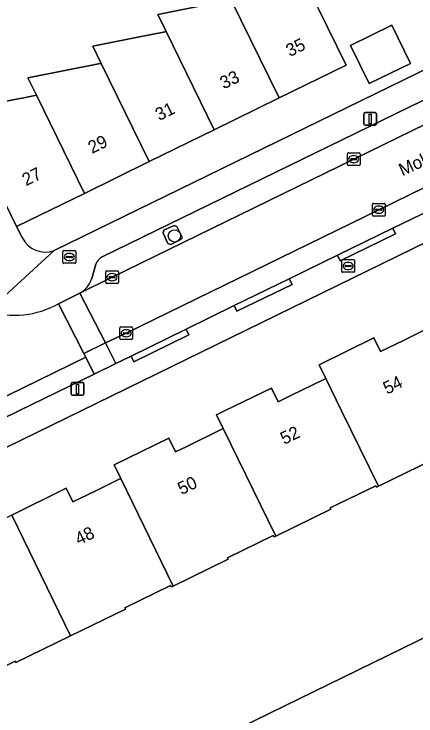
# Model space of a CAD drawing. Extents: x 160455 to 162082, y 388339 to 389736.
# Drawn here: x 160872.8 to 160904.5, y 388725.9 to 388781.3 of the extents above; entities that cross this region are included whole.
import ezdxf

# ---------------------------------------------------------------- set-up
doc = ezdxf.new("R2010")
doc.units = 0
for name, color, linetype in [('IMGEO_Boom', 7, 'Continuous'), ('IMGEO_Brandkraan', 7, 'Continuous'), ('IMGEO_Erf', 7, 'Continuous'), ('IMGEO_Groenvoorziening', 7, 'Continuous'), ('IMGEO_Kolk', 7, 'Continuous'), ('IMGEO_Lichtmast', 7, 'Continuous'), ('IMGEO_Openbare_ruimte_label', 7, 'Continuous'), ('IMGEO_Pand', 7, 'Continuous'), ('IMGEO_Pand_nummerreeks', 7, 'Continuous'), ('IMGEO_Parkeervlak_open', 7, 'Continuous'), ('IMGEO_Rijbaan_lokaal_gesloten', 7, 'Continuous'), ('IMGEO_Rijbaan_lokaal_open', 7, 'Continuous'), ('IMGEO_Voetpad_open', 7, 'Continuous'), ('IMGEO_Waterloop', 7, 'Continuous')]:
    doc.layers.add(name, color=color, linetype=linetype)

msp = doc.modelspace()

# ---------------------------------------------------------------- linework, layer by layer
at = {"layer": 'IMGEO_Boom'}
msp.add_circle((160885.427, 388763.797), 0.489, dxfattribs=at)
at = {"layer": 'IMGEO_Brandkraan'}
for p, q in [((160876.642, 388761.709), (160876.642, 388762.561)), ((160876.717, 388762.635), (160877.569, 388762.635)), ((160877.643, 388762.561), (160877.643, 388761.709)), ((160876.901, 388762.129), (160876.901, 388762.141)), ((160877.339, 388762.092), (160876.941, 388762.092)), ((160876.944, 388762.178), (160877.342, 388762.178)), ((160877.13, 388762.415), (160877.155, 388762.415)), ((160877.385, 388762.141), (160877.385, 388762.129)), ((160877.569, 388761.635), (160876.717, 388761.635)), ((160877.153, 388761.855), (160877.128, 388761.855)), ((160898.623, 388761.001), (160898.623, 388761.853)), ((160898.698, 388761.927), (160899.55, 388761.927)), ((160898.882, 388761.421), (160898.882, 388761.433)), ((160898.925, 388761.47), (160899.323, 388761.47)), ((160899.111, 388761.707), (160899.136, 388761.707)), ((160899.366, 388761.433), (160899.366, 388761.421)), ((160899.624, 388761.853), (160899.624, 388761.001)), ((160899.55, 388760.927), (160898.698, 388760.927)), ((160899.32, 388761.384), (160898.922, 388761.384)), ((160899.134, 388761.147), (160899.109, 388761.147))]:
    msp.add_line(p, q, dxfattribs=at)
for points in [[(160876.642, 388761.709), (160876.642, 388762.561)], [(160876.717, 388762.635), (160877.569, 388762.635)], [(160877.643, 388762.561), (160877.643, 388761.709)], [(160877.569, 388761.635), (160876.717, 388761.635)], [(160898.623, 388761.001), (160898.623, 388761.853)], [(160898.698, 388761.927), (160899.55, 388761.927)], [(160899.624, 388761.853), (160899.624, 388761.001)], [(160899.55, 388760.927), (160898.698, 388760.927)]]:
    msp.add_lwpolyline(points, dxfattribs=at)
for centre, radius, start, end in [((160876.719, 388762.559), 0.0765, 91.552, 178.448), ((160876.719, 388762.559), 0.0765, 91.552, 178.448), ((160877.567, 388762.559), 0.0765, 1.552, 88.448), ((160877.567, 388762.559), 0.0765, 1.552, 88.448), ((160876.941, 388762.138), 0.0403, 85.8775, 175.7526), ((160876.938, 388762.128), 0.0366, 178.938, 274.7102), ((160877.342, 388762.135), 0.043, 264.8664, 352.4533), ((160877.346, 388762.14), 0.0386, 1.7309, 96.639), ((160876.719, 388761.711), 0.0765, 181.552, 268.448), ((160876.719, 388761.711), 0.0765, 181.552, 268.448), ((160877.567, 388761.711), 0.0765, 271.552, 358.448), ((160877.567, 388761.711), 0.0765, 271.552, 358.448), ((160898.7, 388761.851), 0.0765, 91.552, 178.448), ((160898.7, 388761.851), 0.0765, 91.552, 178.448), ((160898.922, 388761.43), 0.0403, 85.8775, 175.7526), ((160898.919, 388761.42), 0.0366, 178.938, 274.7102), ((160899.323, 388761.427), 0.043, 264.8664, 352.4533), ((160899.327, 388761.432), 0.0386, 1.7309, 96.639), ((160899.548, 388761.851), 0.0765, 1.552, 88.448), ((160899.548, 388761.851), 0.0765, 1.552, 88.448), ((160898.7, 388761.003), 0.0765, 181.552, 268.448), ((160898.7, 388761.003), 0.0765, 181.552, 268.448), ((160899.548, 388761.003), 0.0765, 271.552, 358.448), ((160899.548, 388761.003), 0.0765, 271.552, 358.448)]:
    msp.add_arc(centre, radius, start, end, dxfattribs=at)
for centre, major_axis, ratio, start_param, end_param in [((160877.129, 388762.135), (-0.387, 0.002), 0.722429, 4.712389, 7.853982), ((160877.154, 388762.135), (-0.39, 0.002), 0.717154, 1.570796, 4.712389), ((160899.11, 388761.427), (-0.387, 0.002), 0.722429, 4.712389, 7.853982), ((160899.135, 388761.427), (-0.39, 0.002), 0.717154, 1.570796, 4.712389)]:
    msp.add_ellipse(centre, major_axis=major_axis, ratio=ratio, start_param=start_param, end_param=end_param, dxfattribs=at)
at = {"layer": 'IMGEO_Erf'}
for points in [[(160875.947, 388762.656), (160922.127, 388785.223)], [(160868.516, 388773.685), (160872.989, 388774.58), (160873.419, 388774.666), (160874.321, 388774.847), (160874.546, 388774.892), (160873.883, 388776.248), (160876.661, 388776.801), (160879.438, 388777.354), (160879.663, 388777.399), (160879, 388778.755), (160882.554, 388779.462), (160884.555, 388779.861), (160884.78, 388779.906), (160884.117, 388781.262), (160887.932, 388782.021)], [(160896.769, 388781.756), (160898.969, 388777.266), (160893.681, 388774.675), (160888.563, 388772.168), (160883.446, 388769.66), (160878.329, 388767.153), (160872.977, 388764.531), (160873.431, 388763.666)], [(160937.925, 388772.412), (160936.05, 388776.299), (160935.249, 388777.96), (160929.117, 388774.962), (160878.066, 388750), (160811.085, 388717.249)], [(160766.298, 388664.267), (160941.708, 388750), (160948.921, 388753.525), (160948.021, 388755.303), (160947.977, 388755.282), (160946.576, 388758.143), (160949.559, 388759.604), (160949.905, 388758.897), (160955.447, 388761.62), (160953.756, 388765.074), (160956.812, 388766.571), (160958.502, 388763.122), (160958.774, 388763.255), (160957.453, 388765.953), (160960.515, 388767.453), (160961.835, 388764.759), (160968.352, 388767.962)], [(160872.599, 388741.787), (160876.898, 388743.896), (160877.427, 388742.819), (160879.228, 388743.7), (160881.029, 388744.581), (160881.194, 388744.662), (160880.669, 388745.741), (160884.978, 388747.842), (160885.505, 388746.764), (160886.34, 388747.173), (160889.113, 388748.532), (160889.269, 388748.608), (160888.742, 388749.687), (160889.385, 388750), (160893.068, 388751.796), (160893.594, 388750.717), (160894.654, 388751.238), (160897.195, 388752.486), (160897.351, 388752.562), (160896.824, 388753.641), (160901.153, 388755.751), (160901.679, 388754.672), (160903.479, 388755.554), (160905.278, 388756.436)], [(160905.828, 388746.18), (160901.5, 388744.065), (160901.355, 388743.994), (160901.303, 388744.102), (160897.696, 388742.348), (160897.749, 388742.24), (160893.408, 388740.129), (160893.261, 388740.058), (160893.209, 388740.166), (160889.603, 388738.412), (160889.655, 388738.304), (160885.316, 388736.194), (160885.168, 388736.122), (160885.115, 388736.23), (160881.509, 388734.476), (160881.562, 388734.368), (160877.233, 388732.263), (160872.919, 388730.166), (160872.867, 388730.274), (160869.261, 388728.52)]]:
    msp.add_lwpolyline(points, dxfattribs=at)
msp.add_lwpolyline([(160899.294, 388778.812), (160902.551, 388780.407), (160904.026, 388777.398), (160900.769, 388775.802)], close=True, dxfattribs=at)
msp.add_arc((160875.231, 388764.512), 1.989, 205.1625, 291.0934, dxfattribs=at)
at = {"layer": 'IMGEO_Groenvoorziening'}
msp.add_lwpolyline([(160886.012, 388763.755), (160885.625, 388764.551), (160885.403, 388764.625), (160884.59, 388764.237), (160884.53, 388764.012), (160884.92, 388763.211), (160885.146, 388763.123), (160885.938, 388763.517)], dxfattribs=at)
msp.add_arc((160885.855, 388763.673), 0.177, 298.0228, 27.4337, dxfattribs=at)
at = {"layer": 'IMGEO_Kolk'}
for p, q in [((160899.059, 388769.421), (160899.059, 388770.273)), ((160899.134, 388770.347), (160899.986, 388770.347)), ((160900.06, 388770.273), (160900.06, 388769.421)), ((160899.318, 388769.841), (160899.318, 388769.853)), ((160899.756, 388769.804), (160899.358, 388769.804)), ((160899.361, 388769.89), (160899.759, 388769.89)), ((160899.547, 388770.127), (160899.572, 388770.127)), ((160899.802, 388769.853), (160899.802, 388769.841)), ((160899.986, 388769.347), (160899.134, 388769.347)), ((160899.57, 388769.567), (160899.545, 388769.567)), ((160901.034, 388765.438), (160901.034, 388766.29)), ((160901.109, 388766.364), (160901.961, 388766.364)), ((160901.293, 388765.858), (160901.293, 388765.87)), ((160901.336, 388765.907), (160901.734, 388765.907)), ((160901.522, 388766.144), (160901.547, 388766.144)), ((160901.777, 388765.87), (160901.777, 388765.858)), ((160902.035, 388766.29), (160902.035, 388765.438)), ((160901.961, 388765.364), (160901.109, 388765.364)), ((160901.731, 388765.821), (160901.333, 388765.821)), ((160901.545, 388765.584), (160901.52, 388765.584)), ((160880.009, 388760.12), (160880.009, 388760.972)), ((160880.084, 388761.046), (160880.936, 388761.046)), ((160881.01, 388760.972), (160881.01, 388760.12)), ((160880.268, 388760.54), (160880.268, 388760.552)), ((160880.706, 388760.503), (160880.308, 388760.503)), ((160880.311, 388760.589), (160880.709, 388760.589)), ((160880.497, 388760.826), (160880.522, 388760.826)), ((160880.752, 388760.552), (160880.752, 388760.54)), ((160880.936, 388760.046), (160880.084, 388760.046)), ((160880.52, 388760.266), (160880.495, 388760.266)), ((160881.116, 388755.698), (160881.116, 388756.55)), ((160881.191, 388756.624), (160882.043, 388756.624)), ((160882.117, 388756.55), (160882.117, 388755.698)), ((160881.375, 388756.118), (160881.375, 388756.13)), ((160881.813, 388756.081), (160881.415, 388756.081)), ((160881.418, 388756.167), (160881.816, 388756.167)), ((160881.604, 388756.404), (160881.629, 388756.404)), ((160881.859, 388756.13), (160881.859, 388756.118)), ((160882.043, 388755.624), (160881.191, 388755.624)), ((160881.627, 388755.844), (160881.602, 388755.844))]:
    msp.add_line(p, q, dxfattribs=at)
for points in [[(160899.059, 388769.421), (160899.059, 388770.273)], [(160899.134, 388770.347), (160899.986, 388770.347)], [(160900.06, 388770.273), (160900.06, 388769.421)], [(160899.986, 388769.347), (160899.134, 388769.347)], [(160901.034, 388765.438), (160901.034, 388766.29)], [(160901.109, 388766.364), (160901.961, 388766.364)], [(160902.035, 388766.29), (160902.035, 388765.438)], [(160901.961, 388765.364), (160901.109, 388765.364)], [(160880.009, 388760.12), (160880.009, 388760.972)], [(160880.084, 388761.046), (160880.936, 388761.046)], [(160881.01, 388760.972), (160881.01, 388760.12)], [(160880.936, 388760.046), (160880.084, 388760.046)], [(160881.116, 388755.698), (160881.116, 388756.55)], [(160881.191, 388756.624), (160882.043, 388756.624)], [(160882.117, 388756.55), (160882.117, 388755.698)], [(160882.043, 388755.624), (160881.191, 388755.624)]]:
    msp.add_lwpolyline(points, dxfattribs=at)
for centre, radius, start, end in [((160899.136, 388770.271), 0.0765, 91.552, 178.448), ((160899.136, 388770.271), 0.0765, 91.552, 178.448), ((160899.984, 388770.271), 0.0765, 1.552, 88.448), ((160899.984, 388770.271), 0.0765, 1.552, 88.448), ((160899.358, 388769.85), 0.0403, 85.8775, 175.7526), ((160899.355, 388769.84), 0.0366, 178.938, 274.7102), ((160899.759, 388769.847), 0.043, 264.8664, 352.4533), ((160899.763, 388769.852), 0.0386, 1.7309, 96.639), ((160899.136, 388769.423), 0.0765, 181.552, 268.448), ((160899.136, 388769.423), 0.0765, 181.552, 268.448), ((160899.984, 388769.423), 0.0765, 271.552, 358.448), ((160899.984, 388769.423), 0.0765, 271.552, 358.448), ((160901.111, 388766.288), 0.0765, 91.552, 178.448), ((160901.111, 388766.288), 0.0765, 91.552, 178.448), ((160901.333, 388765.867), 0.0403, 85.8775, 175.7526), ((160901.33, 388765.857), 0.0366, 178.938, 274.7102), ((160901.734, 388765.864), 0.043, 264.8664, 352.4533), ((160901.738, 388765.869), 0.0386, 1.7309, 96.639), ((160901.959, 388766.288), 0.0765, 1.552, 88.448), ((160901.959, 388766.288), 0.0765, 1.552, 88.448), ((160901.111, 388765.44), 0.0765, 181.552, 268.448), ((160901.111, 388765.44), 0.0765, 181.552, 268.448), ((160901.959, 388765.44), 0.0765, 271.552, 358.448), ((160901.959, 388765.44), 0.0765, 271.552, 358.448), ((160880.086, 388760.97), 0.0765, 91.552, 178.448), ((160880.086, 388760.97), 0.0765, 91.552, 178.448), ((160880.934, 388760.97), 0.0765, 1.552, 88.448), ((160880.934, 388760.97), 0.0765, 1.552, 88.448), ((160880.308, 388760.549), 0.0403, 85.8775, 175.7526), ((160880.305, 388760.539), 0.0366, 178.938, 274.7102), ((160880.709, 388760.546), 0.043, 264.8664, 352.4533), ((160880.713, 388760.551), 0.0386, 1.7309, 96.639), ((160880.086, 388760.122), 0.0765, 181.552, 268.448), ((160880.086, 388760.122), 0.0765, 181.552, 268.448), ((160880.934, 388760.122), 0.0765, 271.552, 358.448), ((160880.934, 388760.122), 0.0765, 271.552, 358.448), ((160881.193, 388756.548), 0.0765, 91.552, 178.448), ((160881.193, 388756.548), 0.0765, 91.552, 178.448), ((160882.041, 388756.548), 0.0765, 1.552, 88.448), ((160882.041, 388756.548), 0.0765, 1.552, 88.448), ((160881.415, 388756.127), 0.0403, 85.8775, 175.7526), ((160881.412, 388756.117), 0.0366, 178.938, 274.7102), ((160881.816, 388756.124), 0.043, 264.8664, 352.4533), ((160881.82, 388756.129), 0.0386, 1.7309, 96.639), ((160881.193, 388755.7), 0.0765, 181.552, 268.448), ((160881.193, 388755.7), 0.0765, 181.552, 268.448), ((160882.041, 388755.7), 0.0765, 271.552, 358.448), ((160882.041, 388755.7), 0.0765, 271.552, 358.448)]:
    msp.add_arc(centre, radius, start, end, dxfattribs=at)
for centre, major_axis, ratio, start_param, end_param in [((160899.546, 388769.847), (-0.387, 0.002), 0.722429, 4.712389, 7.853982), ((160899.571, 388769.847), (-0.39, 0.002), 0.717154, 1.570796, 4.712389), ((160901.521, 388765.864), (-0.387, 0.002), 0.722429, 4.712389, 7.853982), ((160901.546, 388765.864), (-0.39, 0.002), 0.717154, 1.570796, 4.712389), ((160880.496, 388760.546), (-0.387, 0.002), 0.722429, 4.712389, 7.853982), ((160880.521, 388760.546), (-0.39, 0.002), 0.717154, 1.570796, 4.712389), ((160881.603, 388756.124), (-0.387, 0.002), 0.722429, 4.712389, 7.853982), ((160881.628, 388756.124), (-0.39, 0.002), 0.717154, 1.570796, 4.712389)]:
    msp.add_ellipse(centre, major_axis=major_axis, ratio=ratio, start_param=start_param, end_param=end_param, dxfattribs=at)
at = {"layer": 'IMGEO_Lichtmast'}
for p, q in [((160900.353, 388772.618), (160900.353, 388773.418)), ((160900.353, 388773.418), (160900.353, 388772.618)), ((160900.453, 388773.518), (160901.243, 388773.518)), ((160901.243, 388773.518), (160900.453, 388773.518)), ((160901.343, 388773.418), (160901.343, 388772.618)), ((160901.343, 388772.618), (160901.343, 388773.418)), ((160901.243, 388772.518), (160900.453, 388772.518)), ((160900.453, 388772.518), (160901.243, 388772.518)), ((160877.287, 388751.332), (160877.287, 388752.132)), ((160877.287, 388752.132), (160877.287, 388751.332)), ((160877.387, 388752.232), (160878.177, 388752.232)), ((160878.177, 388752.232), (160877.387, 388752.232)), ((160878.277, 388752.132), (160878.277, 388751.332)), ((160878.277, 388751.332), (160878.277, 388752.132)), ((160878.177, 388751.232), (160877.387, 388751.232)), ((160877.387, 388751.232), (160878.177, 388751.232))]:
    msp.add_line(p, q, dxfattribs=at)
for points in [[(160900.773, 388773.393), (160900.923, 388773.393), (160900.923, 388772.643), (160900.773, 388772.643), (160900.773, 388773.393)], [(160877.707, 388752.107), (160877.857, 388752.107), (160877.857, 388751.357), (160877.707, 388751.357), (160877.707, 388752.107)]]:
    msp.add_lwpolyline(points, dxfattribs=at)
for centre, start, end in [((160900.453, 388773.418), 90, 180), ((160900.453, 388773.418), 90, 180), ((160901.243, 388773.418), 0, 90), ((160901.243, 388773.418), 360, 90), ((160900.453, 388772.618), 180, 270), ((160900.453, 388772.618), 180, 270), ((160901.243, 388772.618), 270, 0), ((160901.243, 388772.618), 270, 0), ((160877.387, 388752.132), 90, 180), ((160877.387, 388752.132), 90, 180), ((160878.177, 388752.132), 0, 90), ((160878.177, 388752.132), 360, 90), ((160877.387, 388751.332), 180, 270), ((160877.387, 388751.332), 180, 270), ((160878.177, 388751.332), 270, 0), ((160878.177, 388751.332), 270, 0)]:
    msp.add_arc(centre, 0.1, start, end, dxfattribs=at)
at = {"layer": 'IMGEO_Pand'}
for points in [[(160889.897, 388782.413), (160893.681, 388774.675), (160898.969, 388777.266), (160896.769, 388781.756), (160895.228, 388784.923), (160894.367, 388786.694), (160889.07, 388784.103), (160889.234, 388783.768)], [(160889.897, 388782.413), (160889.672, 388782.368), (160887.932, 388782.021), (160884.117, 388781.262), (160884.78, 388779.906), (160888.563, 388772.168), (160893.681, 388774.675)], [(160899.294, 388778.812), (160900.769, 388775.802), (160904.026, 388777.398), (160902.551, 388780.407)], [(160884.78, 388779.906), (160884.555, 388779.861), (160882.554, 388779.462), (160879, 388778.755), (160879.663, 388777.399), (160883.446, 388769.66), (160888.563, 388772.168)], [(160879.663, 388777.399), (160879.438, 388777.354), (160876.661, 388776.801), (160873.883, 388776.248), (160874.546, 388774.892), (160878.329, 388767.153), (160883.446, 388769.66)], [(160874.546, 388774.892), (160874.321, 388774.847), (160873.419, 388774.666), (160872.989, 388774.58), (160868.516, 388773.685), (160872.977, 388764.531), (160878.329, 388767.153)], [(160905.432, 388756.511), (160905.278, 388756.436), (160903.479, 388755.554), (160901.679, 388754.672), (160901.153, 388755.751), (160896.824, 388753.641), (160897.351, 388752.562), (160898.602, 388750), (160901.5, 388744.065), (160905.828, 388746.18), (160905.775, 388746.288), (160906.545, 388746.665), (160909.385, 388748.052), (160909.532, 388748.124), (160908.615, 388750)], [(160897.351, 388752.562), (160897.195, 388752.486), (160894.654, 388751.238), (160893.594, 388750.717), (160893.068, 388751.796), (160889.385, 388750), (160888.742, 388749.687), (160889.269, 388748.608), (160893.408, 388740.129), (160897.749, 388742.24), (160897.696, 388742.348), (160901.303, 388744.102), (160901.355, 388743.994), (160901.5, 388744.065), (160898.602, 388750)], [(160889.269, 388748.608), (160889.113, 388748.532), (160886.34, 388747.173), (160885.505, 388746.764), (160884.978, 388747.842), (160880.669, 388745.741), (160881.194, 388744.662), (160885.316, 388736.194), (160889.655, 388738.304), (160889.603, 388738.412), (160893.209, 388740.166), (160893.261, 388740.058), (160893.408, 388740.129)], [(160881.194, 388744.662), (160881.029, 388744.581), (160879.228, 388743.7), (160877.427, 388742.819), (160876.898, 388743.896), (160872.599, 388741.787), (160877.233, 388732.263), (160881.562, 388734.368), (160881.509, 388734.476), (160885.115, 388736.23), (160885.168, 388736.122), (160885.316, 388736.194)], [(160872.599, 388741.787), (160868.282, 388739.669), (160868.811, 388738.592), (160867.913, 388738.157), (160865.201, 388736.843), (160865.055, 388736.772), (160869.159, 388728.337), (160869.313, 388728.412), (160869.261, 388728.52), (160872.867, 388730.274), (160872.919, 388730.166), (160877.233, 388732.263)]]:
    msp.add_lwpolyline(points, close=True, dxfattribs=at)
at = {"layer": 'IMGEO_Parkeervlak_open'}
msp.add_lwpolyline([(160927.483, 388776.866), (160927.831, 388777.792), (160928.178, 388778.717), (160928.626, 388779.448), (160927.363, 388778.614), (160926.684, 388778.165), (160901.535, 388765.865), (160881.617, 388756.126), (160879.999, 388755.357), (160880.802, 388753.74), (160882.009, 388754.317), (160886.347, 388756.438), (160890.137, 388758.307), (160894.483, 388760.414), (160898.273, 388762.276), (160902.641, 388764.4), (160906.397, 388766.234), (160910.736, 388768.366), (160914.255, 388770.086), (160918.883, 388772.324), (160922.403, 388774.059), (160926.965, 388776.289)], dxfattribs=at)
for points in [[(160878.433, 388754.232), (160879.107, 388752.907), (160880.802, 388753.74), (160879.999, 388755.357), (160878.277, 388754.538)], [(160860.175, 388745.303), (160860.806, 388743.953), (160873.165, 388750), (160879.107, 388752.907), (160878.433, 388754.232), (160869.779, 388750)]]:
    msp.add_lwpolyline(points, close=True, dxfattribs=at)
at = {"layer": 'IMGEO_Rijbaan_lokaal_gesloten'}
msp.add_lwpolyline([(160923.089, 388781.332), (160922.221, 388780.848), (160922.077, 388780.78), (160918.996, 388779.324), (160899.56, 388769.847), (160880.511, 388760.545), (160877.968, 388759.28), (160879.999, 388755.357), (160881.617, 388756.126), (160901.535, 388765.865), (160926.684, 388778.165), (160927.363, 388778.614), (160928.626, 388779.448), (160929.119, 388780.101)], dxfattribs=at)
at = {"layer": 'IMGEO_Rijbaan_lokaal_open'}
msp.add_lwpolyline([(160878.277, 388754.538), (160879.999, 388755.357), (160877.968, 388759.28), (160876.286, 388758.451)], close=True, dxfattribs=at)
for points in [[(160878.433, 388754.232), (160878.277, 388754.538), (160876.286, 388758.451)], [(160858.828, 388750), (160858.158, 388749.617), (160859.667, 388746.388), (160860.028, 388745.616), (160860.175, 388745.303), (160869.779, 388750), (160878.433, 388754.232)]]:
    msp.add_lwpolyline(points, dxfattribs=at)
msp.add_arc((160872.838, 388764.541), 6.998, 252.3018, 299.5161, dxfattribs=at)
at = {"layer": 'IMGEO_Voetpad_open'}
for points in [[(160922.127, 388785.223), (160875.947, 388762.656), (160870.711, 388757.874)], [(160877.968, 388759.28), (160880.511, 388760.545), (160899.56, 388769.847), (160918.996, 388779.324), (160922.077, 388780.78)], [(160918.637, 388781.134), (160879.737, 388762.15)], [(160879.737, 388762.15), (160918.637, 388781.134)], [(160878.066, 388750), (160929.117, 388774.962), (160927.831, 388777.792), (160927.483, 388776.866)], [(160873.431, 388763.666), (160872.977, 388764.531), (160868.516, 388773.685)], [(160906.397, 388766.234), (160902.641, 388764.4), (160902.859, 388763.951), (160898.491, 388761.827), (160898.273, 388762.276), (160894.483, 388760.414), (160894.701, 388759.965), (160890.355, 388757.858), (160890.137, 388758.307), (160886.347, 388756.438), (160886.566, 388755.989), (160882.228, 388753.868), (160882.009, 388754.317), (160880.802, 388753.74), (160879.107, 388752.907), (160873.165, 388750), (160860.806, 388743.953)], [(160885.938, 388763.517), (160885.146, 388763.123), (160884.92, 388763.211), (160884.53, 388764.012), (160884.59, 388764.237), (160885.403, 388764.625), (160885.625, 388764.551), (160886.012, 388763.755)], [(160870.711, 388757.874), (160875.947, 388762.656)], [(160879.241, 388761.568), (160878.906, 388760.432)], [(160878.906, 388760.432), (160879.241, 388761.568)], [(160876.286, 388758.451), (160877.968, 388759.28)], [(160816.666, 388724.342), (160815.673, 388723.851), (160815.893, 388723.403), (160809.661, 388720.335), (160811.085, 388717.249), (160878.066, 388750)]]:
    msp.add_lwpolyline(points, dxfattribs=at)
for points in [[(160902.641, 388764.4), (160898.273, 388762.276), (160898.491, 388761.827), (160902.859, 388763.951)], [(160890.137, 388758.307), (160890.355, 388757.858), (160894.701, 388759.965), (160894.483, 388760.414)], [(160882.009, 388754.317), (160882.228, 388753.868), (160886.566, 388755.989), (160886.347, 388756.438)]]:
    msp.add_lwpolyline(points, close=True, dxfattribs=at)
for centre, radius, start, end in [((160875.231, 388764.512), 1.989, 205.1625, 291.0934), ((160885.855, 388763.673), 0.177, 298.0228, 27.4337), ((160880.179, 388761.271), 0.984, 116.6912, 162.4312), ((160880.179, 388761.271), 0.984, 116.6912, 162.4312), ((160876.995, 388761.03), 2.002, 299.0667, 342.6259), ((160876.995, 388761.03), 2.002, 299.0667, 342.6259), ((160872.838, 388764.541), 6.998, 252.3018, 299.5161)]:
    msp.add_arc(centre, radius, start, end, dxfattribs=at)
at = {"layer": 'IMGEO_Waterloop'}
msp.add_lwpolyline([(160956.23, 388750), (160986.989, 388765.073), (161000, 388771.638), (161004.045, 388773.679), (161001.348, 388779.301), (161000, 388778.665), (160998.756, 388778.042), (160985.165, 388771.24), (160948.921, 388753.525), (160941.708, 388750), (160766.298, 388664.267), (160769.08, 388658.493), (160783.435, 388665.323)], close=True, dxfattribs=at)

# ---------------------------------------------------------------- texts
at = {"layer": 'IMGEO_Openbare_ruimte_label'}
msp.add_text('Molièrelaan', height=1, rotation=24.8992, dxfattribs=at).set_placement((160903.398, 388768.493))
at = {"layer": 'IMGEO_Pand_nummerreeks'}
for s, rotation, p in [('35', 26.104, (160894.519, 388777.892)), ('33', 26.104, (160889.32, 388775.345)), ('31', 26.104, (160884.224, 388772.848)), ('29', 26.104, (160878.924, 388770.251)), ('27', 26.104, (160873.725, 388767.704)), ('54', 26.0696, (160902.183, 388751.275)), ('52', 26.0696, (160894.082, 388747.312)), ('50', 26.0696, (160885.99, 388743.353)), ('48', 26.0696, (160877.892, 388739.391))]:
    msp.add_text(s, height=1, rotation=rotation, dxfattribs=at).set_placement(p)

doc.saveas('drawing.dxf')
